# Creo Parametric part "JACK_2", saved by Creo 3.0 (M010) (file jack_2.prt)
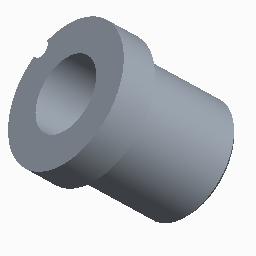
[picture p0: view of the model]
Units: millimeter Newton Second (mmNs); MM, TONNE, SECS

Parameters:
  PLACEMENT = "INTERNAL"

Other parameters: MINOR_DIAMETER, PITCH

Created from: MMNS_PART_SOLID.PRT

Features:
  1. datum plane "RIGHT"
  2. datum plane "TOP"
  3. datum plane "FRONT"
  4. coordinate system
  5. protrusion
  6. hole
  7. chamfer
  8. cut

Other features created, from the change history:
  planar section "A2-2"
